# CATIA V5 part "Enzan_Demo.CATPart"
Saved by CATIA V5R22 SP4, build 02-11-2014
Part number: Enzan_Demo
Bounding box of the stored display mesh (mm): x -75 to 75, y 275 to 365, z -46.667 to 33.333
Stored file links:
  C:\DATA\Car_ASSY\教育モデル\0_DEMO\Enzan_Demo.CATPart
  C:\DATA\HD2_R22\R22_02_PDG\pd10_enzan.CATPart
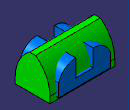
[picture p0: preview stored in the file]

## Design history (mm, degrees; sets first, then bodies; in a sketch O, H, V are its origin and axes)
Body1 (main body)
Body2 "Ao"
  Sketch1, origin (0, 320, 0), H (-1, 0, 0), V (0, 0, 1)
    line L1 (-59.7007, -40) -> (60.2993, -40)
    line L2 (60.2993, -40) -> (60.2993, -10)
    arc A1 centre (20.2993, -21.6667) radius 41.6667 from (60.2993, -10) to (20.2993, 20) ccw
    point P4 (20.2993, -21.6667)
    line L3 (20.2993, 20) -> (20.2993, -20)
    line L4 (20.2993, -20) -> (-19.7007, -20)
    line L5 (-19.7007, -20) -> (-19.7007, 20)
    arc A2 centre (-19.7007, -21.6667) radius 41.6667 from (-19.7007, 20) to (-59.7007, -10) ccw
    point P9 (-19.7007, -21.6667)
    line L6 (-59.7007, -10) -> (-59.7007, -40)
    distance L2 L6 = 120
    length L2 = 30
    length L6 = 30
    distance L4 L1 = 20
    distance L1 H = 40
    distance L5 L6 = 40
    distance L5 L3 = 40
    distance L1 A1 = 60
    distance L1 A2 = 60
    horizontal: L1 H
    vertical: L2 V
    coincidence: P9 L5, P4 L3
  Pad1: profile Sketch1, direction (0, 1, 0), length 45, mirrored extent
Body3 "Midori"
  Sketch2 on yz-plane, origin (0, 0, 0), H (0, 1, 0), V (0, 0, 1)
    line L1 (280, -46.6667) -> (360, -46.6667)
    line L2 (360, -46.6667) -> (360, -31.6667)
    arc A1 centre (280, -31.6667) radius 80 from (360, -31.6667) to (326.6369, 33.3333) ccw
    line L3 (326.6369, 33.3333) -> (313.3631, 33.3333)
    arc A2 centre (360, -31.6667) radius 80 from (313.3631, 33.3333) to (280, -31.6667) ccw
    line L4 (280, -31.6667) -> (280, -46.6667)
    reference projected line E1 through (0, -21.6667) direction (1, 0) from axis of face of Pad1
    reference intersected line E2 through (320, 0) direction (0, 1)
    distance E1 L1 = 25
    distance E2 L2 = 40
    distance L2 L4 = 80
    radius A2 = 80
    radius A1 = 80
    length L2 = 15
    length L4 = 15
    distance L1 L3 = 80
    vertical: L2 V
    tangency: A1 L2, L4 A2
  Pad2: profile Sketch2, direction (1, 0, 0), length 75, mirrored extent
